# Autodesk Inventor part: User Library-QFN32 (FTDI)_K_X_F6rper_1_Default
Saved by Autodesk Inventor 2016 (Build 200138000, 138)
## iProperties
Created: 2012-01
Part Number: User Library-QFN32 (FTDI)_K_X_F6rper_1_Default
Document SubType Name: Modeling
Designer: Trevor
Density: 1 g/cm^3
Material: Generic
Appearance: Default
Author: Trevor
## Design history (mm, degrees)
feature "Base1"
node "Imported1"
